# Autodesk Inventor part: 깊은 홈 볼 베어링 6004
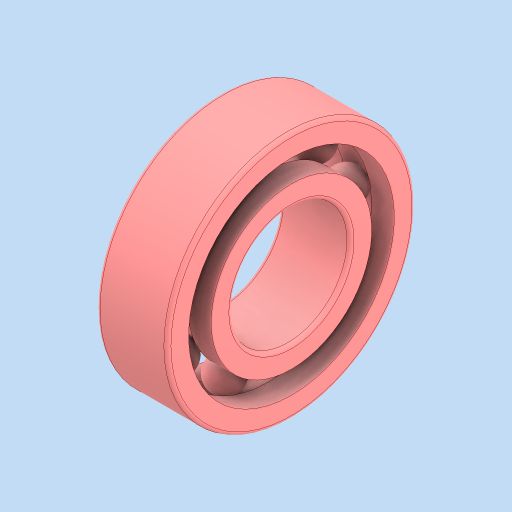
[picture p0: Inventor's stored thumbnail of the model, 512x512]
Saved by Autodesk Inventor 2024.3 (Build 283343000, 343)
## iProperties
Created: 2025-11
Part Number: 깊은 홈 볼 베어링 6004
Material: 강철, 연강
Description: 깊은 그루브 볼 베어링
Document SubType Name: Modeling
Designer: PC2-03
Density: 7.85 g/cm^3
Appearance: 기본값
Author: jhkim
Sending System: Autodesk Inventor 2026
Preprocessor: ST-DEVELOPER v20.1
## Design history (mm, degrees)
feature "Solid1"
feature "Solid1:1"
feature "Solid1:2"
feature "Solid1:3"
feature "Solid1:4"
feature "Solid1:5"
feature "Solid1:6"
feature "Solid1:7"
feature "Solid1:8"
feature "Solid1:9"
feature "Solid1:10"
node "솔리드1"
node "솔리드2"
node "솔리드3"
node "솔리드4"
node "솔리드5"
node "솔리드6"
node "솔리드7"
node "솔리드8"
node "솔리드9"
node "솔리드10"
node "솔리드11"
